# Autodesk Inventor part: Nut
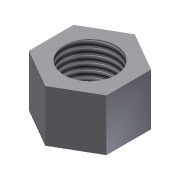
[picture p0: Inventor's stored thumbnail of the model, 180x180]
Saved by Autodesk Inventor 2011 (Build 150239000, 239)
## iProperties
Created: 2010-03
Part Number: Nut
Document SubType Name: Modeling
Designer: bhakira
Density: 1 g/cm^3
Author: bhakira
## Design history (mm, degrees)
sketch "Sketch1"
  geometry: L1 (0, 17.321)-(15, 8.66); L2 (15, 8.66)-(15, -8.66); L3 (15, -8.66)-(0, -17.321); L4 (0, -17.321)-(-15, -8.66); L5 (-15, -8.66)-(-15, 8.66); L6 (-15, 8.66)-(0, 17.321); 2 further points
  constraints: 12 end point, 1 coincident, 13 other
  dimensions: "d0" = 30 distance between parallel lines of L2 L5
extrude "Extrusion1" new body sketch "Sketch1" distance "d1" = 20; taper "d2" = 0 deg
sketch "Sketch2"
  geometry: L1 (0, 17.321)-(-15, 8.66) reference; L2 (-15, 8.66)-(-15, -8.66) reference; L3 (-15, -8.66)-(0, -17.321) reference; L4 (0, -17.321)-(15, -8.66) reference; L5 (15, -8.66)-(15, 8.66) reference; L6 (15, 8.66)-(0, 17.321) reference
sketch "Sketch3"
  geometry: C1 r 10 at (0, 0); 1 further point
  constraints: 1 centre point, 1 coincident
  dimensions: "d4" = 20 diameter of C1
extrude "Extrusion2" cut sketch "Sketch3" stored distance "d5" = 15; taper "d6" = 0 deg
thread "Thread1" dims "d7" = 10, "d8" = 0
body "Solid1"
